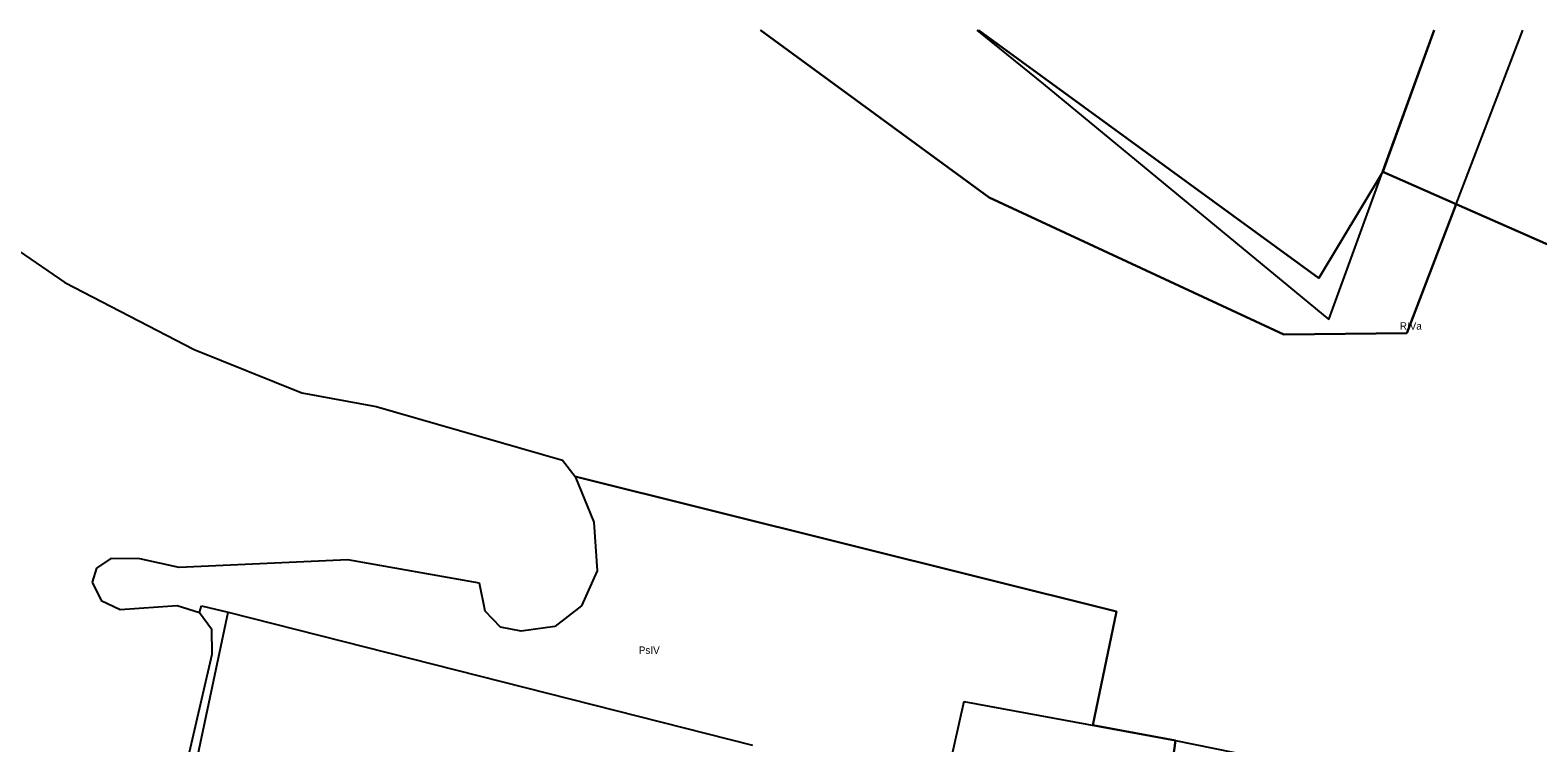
# Model space of a CAD drawing. Extents: x 7498273 to 7499989, y 5499795 to 5500810.
# Drawn here: x 7498588.9 to 7498893.9, y 5500665.5 to 5500809.6 of the extents above; entities that cross this region are included whole.
import ezdxf

# ---------------------------------------------------------------- set-up
doc = ezdxf.new("R2010")
doc.units = 0
for name, color, linetype in [('209-oznaczenie konturu klasyfikacyjnego', 7, 'Continuous'), ('217-kontur klasyfikacyjny', 7, 'Continuous'), ('218-kontur użytku gruntowego', 7, 'Continuous'), ('219-działka ewidencyjna', 7, 'Continuous')]:
    doc.layers.add(name, color=color, linetype=linetype)

msp = doc.modelspace()

# ---------------------------------------------------------------- linework, layer by layer
at = {"layer": '217-kontur klasyfikacyjny'}
for points in [[(7498782.91, 5500775.7), (7498736.648, 5500809.555)], [(7498780.767, 5500809.555), (7498849.58, 5500759.44)], [(7498862.5, 5500780.92), (7498872.913, 5500809.555)], [(7498877.37, 5500774.38), (7498890.827, 5500809.555)], [(7498558.87, 5500783.88), (7498595.9, 5500758.56)], [(7498849.58, 5500759.44), (7498862.5, 5500780.92)], [(7498877.37, 5500774.38), (7498862.5, 5500780.92)], [(7498842.52, 5500748.01), (7498782.91, 5500775.7)], [(7498877.37, 5500774.38), (7498867.39, 5500748.29)], [(7498947.36, 5500743.6), (7498877.37, 5500774.38)], [(7498595.9, 5500758.56), (7498622.11, 5500744.98)], [(7498867.39, 5500748.29), (7498842.52, 5500748.01)], [(7498622.11, 5500744.98), (7498643.86, 5500736.23)], [(7498643.86, 5500736.23), (7498658.91, 5500733.49)], [(7498658.91, 5500733.49), (7498696.57, 5500722.61)], [(7498696.57, 5500722.61), (7498699.14, 5500719.35)], [(7498699.14, 5500719.35), (7498808.69, 5500692.04)], [(7498699.14, 5500719.35), (7498702.94, 5500710.07)], [(7498702.94, 5500710.07), (7498703.62, 5500700.24)], [(7498602.33, 5500700.79), (7498601.47, 5500697.97)], [(7498605.23, 5500702.75), (7498602.33, 5500700.79)], [(7498611.08, 5500702.71), (7498605.23, 5500702.75)], [(7498619.03, 5500700.91), (7498611.08, 5500702.71)], [(7498653.14, 5500702.45), (7498619.03, 5500700.91)], [(7498679.8, 5500697.76), (7498653.14, 5500702.45)], [(7498703.62, 5500700.24), (7498700.46, 5500693.15)], [(7498601.47, 5500697.97), (7498603.27, 5500694.29)], [(7498680.97, 5500692.09), (7498679.8, 5500697.76)], [(7498603.27, 5500694.29), (7498607.11, 5500692.41)], [(7498607.11, 5500692.41), (7498618.66, 5500693.26)], [(7498618.66, 5500693.26), (7498623.19, 5500691.81)], [(7498623.19, 5500691.81), (7498623.54, 5500693.19)], [(7498623.19, 5500691.81), (7498625.58, 5500688.56)], [(7498623.54, 5500693.19), (7498628.95, 5500691.93)], [(7498628.95, 5500691.93), (7498735, 5500665.04)], [(7498684.02, 5500688.84), (7498680.97, 5500692.09)], [(7498700.46, 5500693.15), (7498695.02, 5500689)], [(7498808.69, 5500692.04), (7498803.9, 5500669.03)], [(7498625.58, 5500688.56), (7498625.67, 5500683.35)], [(7498688.24, 5500688.03), (7498684.02, 5500688.84)], [(7498695.02, 5500689), (7498688.24, 5500688.03)], [(7498625.67, 5500683.35), (7498618.49, 5500652.49)], [(7498803.9, 5500669.03), (7498820.57, 5500665.94)], [(7498820.57, 5500665.94), (7498819.02, 5500654.66)]]:
    msp.add_lwpolyline(points, dxfattribs=at)
at = {"layer": '218-kontur użytku gruntowego'}
for points in [[(7498736.648, 5500809.555), (7498782.91, 5500775.7)], [(7498849.58, 5500759.44), (7498780.767, 5500809.555)], [(7498872.913, 5500809.555), (7498862.5, 5500780.92)], [(7498877.37, 5500774.38), (7498890.827, 5500809.555)], [(7498558.87, 5500783.88), (7498595.9, 5500758.56)], [(7498862.5, 5500780.92), (7498849.58, 5500759.44)], [(7498862.5, 5500780.92), (7498877.37, 5500774.38)], [(7498782.91, 5500775.7), (7498842.52, 5500748.01)], [(7498867.39, 5500748.29), (7498877.37, 5500774.38)], [(7498877.37, 5500774.38), (7498947.36, 5500743.6)], [(7498595.9, 5500758.56), (7498622.11, 5500744.98)], [(7498842.52, 5500748.01), (7498867.39, 5500748.29)], [(7498622.11, 5500744.98), (7498643.86, 5500736.23)], [(7498643.86, 5500736.23), (7498658.91, 5500733.49)], [(7498658.91, 5500733.49), (7498696.57, 5500722.61)], [(7498696.57, 5500722.61), (7498699.14, 5500719.35)], [(7498808.69, 5500692.04), (7498699.14, 5500719.35)], [(7498699.14, 5500719.35), (7498702.94, 5500710.07)], [(7498702.94, 5500710.07), (7498703.62, 5500700.24)], [(7498602.33, 5500700.79), (7498601.47, 5500697.97)], [(7498605.23, 5500702.75), (7498602.33, 5500700.79)], [(7498611.08, 5500702.71), (7498605.23, 5500702.75)], [(7498619.03, 5500700.91), (7498611.08, 5500702.71)], [(7498653.14, 5500702.45), (7498619.03, 5500700.91)], [(7498679.8, 5500697.76), (7498653.14, 5500702.45)], [(7498703.62, 5500700.24), (7498700.46, 5500693.15)], [(7498601.47, 5500697.97), (7498603.27, 5500694.29)], [(7498680.97, 5500692.09), (7498679.8, 5500697.76)], [(7498603.27, 5500694.29), (7498607.11, 5500692.41)], [(7498607.11, 5500692.41), (7498618.66, 5500693.26)], [(7498618.66, 5500693.26), (7498623.19, 5500691.81)], [(7498623.19, 5500691.81), (7498623.54, 5500693.19)], [(7498623.19, 5500691.81), (7498625.58, 5500688.56)], [(7498623.54, 5500693.19), (7498628.95, 5500691.93)], [(7498628.95, 5500691.93), (7498735, 5500665.04)], [(7498684.02, 5500688.84), (7498680.97, 5500692.09)], [(7498700.46, 5500693.15), (7498695.02, 5500689)], [(7498803.9, 5500669.03), (7498808.69, 5500692.04)], [(7498625.58, 5500688.56), (7498625.67, 5500683.35)], [(7498688.24, 5500688.03), (7498684.02, 5500688.84)], [(7498695.02, 5500689), (7498688.24, 5500688.03)], [(7498625.67, 5500683.35), (7498618.49, 5500652.49)], [(7498820.57, 5500665.94), (7498803.9, 5500669.03)], [(7498819.02, 5500654.66), (7498820.57, 5500665.94)]]:
    msp.add_lwpolyline(points, dxfattribs=at)
at = {"layer": '219-działka ewidencyjna'}
for points in [[(7498780.386, 5500809.555), (7498793.82, 5500798.68)], [(7498851.63, 5500751.04), (7498872.91, 5500809.555)], [(7498793.82, 5500798.68), (7498851.63, 5500751.04)], [(7498618.68, 5500643.51), (7498628.95, 5500691.93)], [(7498628.95, 5500691.93), (7498735, 5500665.04)], [(7498777.8, 5500673.87), (7498773.75, 5500655.79)], [(7498777.8, 5500673.87), (7498820.57, 5500665.94)], [(7498820.57, 5500665.94), (7498919.07, 5500645.93)]]:
    msp.add_lwpolyline(points, dxfattribs=at)

# ---------------------------------------------------------------- texts
at = {"layer": '209-oznaczenie konturu klasyfikacyjnego'}
for s, p in [('RIVa', (7498865.96, 5500749.01)), ('PsIV', (7498712.02, 5500683.47))]:
    msp.add_text(s, height=1.5, dxfattribs=at).set_placement(p)

doc.saveas('drawing.dxf')
